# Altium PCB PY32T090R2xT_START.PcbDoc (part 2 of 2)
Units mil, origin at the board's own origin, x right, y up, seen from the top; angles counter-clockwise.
Board outline 1771.65 x 3866.06 mil, 2 copper layers (Top Layer, Bottom Layer), stack 21 mil thick; 137 components, 162 nets, 557 pads, 319 vias.
Unrouted connection lines stored in the file: 5.
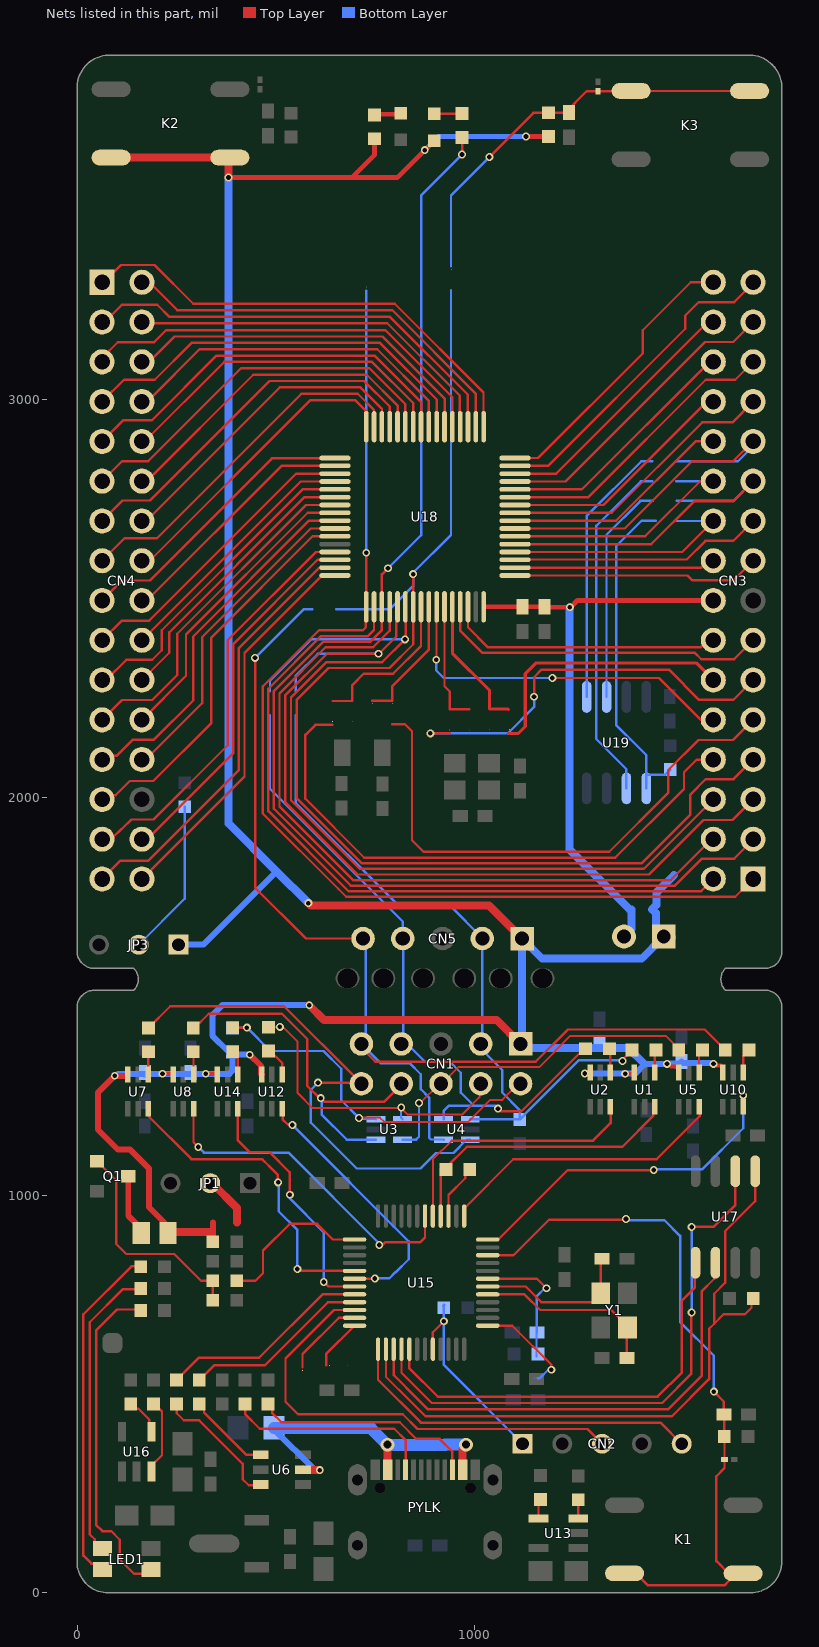
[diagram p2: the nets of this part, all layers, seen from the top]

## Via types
v1: diameter 19.68, hole 11.81, Top Layer to Bottom Layer, 161 vias
v2: diameter 19.68, hole 11.81, Top Layer to Bottom Layer, tented both sides, 146 vias
v3: diameter 35, hole 20, Top Layer to Bottom Layer, tented both sides, 8 vias
v4: diameter 30, hole 15, Top Layer to Bottom Layer, tented both sides, 2 vias
v5: diameter 40, hole 20, Top Layer to Bottom Layer, tented both sides, 2 vias

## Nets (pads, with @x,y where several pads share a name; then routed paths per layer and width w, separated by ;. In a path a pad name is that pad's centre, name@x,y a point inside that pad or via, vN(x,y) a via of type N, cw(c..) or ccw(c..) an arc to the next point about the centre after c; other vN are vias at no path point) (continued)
NetC34_2: C34.2 K3.1 K3.2 R59.2 R60.1 U21.1 | length 1037.5
  Top Layer w6: v1(1036.54,3609.79) 1147.26,3720.51 1226.51,3720.51 1281,3775 U21.1@1309.61,3775 ; U21.1@1309.96,3775.35 1385,3775.35 1385.35,3775.7 K3.1@1393,3775.7 K3.2@1691,3775.7
  Bottom Layer w6: 940,3335 940,3513.24 v1(1036.54,3609.79)
NetJP3_2: JP3.2 R50.1 | length 394.7
  Bottom Layer w6: JP3.2@155,1629.56 270.51,1745.07 R50.1@270.51,1976.45
NetLED1_2: LED1.2 R9.1 | length 846.1
  Top Layer w6: R9.1@160,710 157.67,712.33 100.33,712.33 48,660 48,171 63.8,155.2 85.86,155.2 107.53,133.53 107.53,84.16 143.82,47.87 175.08,47.87 LED1.2@186.02,58.82
NetLED1_3: LED1.3 R6.1 | length 884.3
  Top Layer w6: LED1.3@44.28,58.52 LED1.3@58.98,43.82 ; LED1.3@63.98,58.82 49.28,73.52 36.09,73.52 16,93.61 16,700.34 136.59,820.93 159.07,820.93 R6.1@160,820
NetLED1_4: LED1.4 R4.1 | length 755.1
  Top Layer w6: LED1.4@56.66,98.5 44.36,110.81 44.36,134.74 32,147.09 32,680.34 115.39,763.73 158.73,763.73 R4.1@160,765
NetLED_PA2_2: LED_PA2.2 R45.1 | length 70.4
  Top Layer w6: LED_PA2.2@898,3718 967,3718 R45.1@968,3719
NetLED_VDD*_1: LED_VDD*.1 R38.1 | length 66.4
  Top Layer w12: R38.1@748,3717 813,3717 LED_VDD*.1@814,3718
NetPYLK_A5: PYLK.A5 R1.2 | length 530.3
  Top Layer w6: R1.2@422.49,474.99 422.49,449.82 459.51,412.79 797.58,412.79 825.99,384.38 PYLK.A5@825.99,309.89
NetPYLK_B5: PYLK.B5 R3.1 | length 566
  Top Layer w6: R3.1@480,475 490.31,464.69 490.31,452.34 513.85,428.8 811.11,428.8 852.66,387.24 911.55,387.24 943.17,355.62 943.17,310.82 PYLK.B5@944.1,309.89
NetQ1_1: Q1.1 R19.1 R20.2 | length 559
  Top Layer w6: Q1.1@50,1084.8 51.97,1084.8 63.72,1073.06 63.72,1071.23 98.46,1036.49 98.46,877.34 123.86,851.94 244.45,851.94 311.61,784.78 R19.1@341.53,784.78 ; R20.2@341.52,735.88 R19.1@341.52,784.77
NetQ1_3: Q1.3 R15.1 | length 166.5
  Top Layer w6: Q1.3@125.49,1044.15 Q1.3@128.74,1047.4 ; R15.1@161.54,905 R15.1@161.54,910.91
  Top Layer w15: Q1.3@128.74,1047.4 128.74,948.28 161.54,915.49 R15.1@161.54,905
NetR2_1: R2.1 U1.4 | length 57.9
  Top Layer w6: U1.4@1452.23,1308.31 1452.23,1362.02 R2.1@1455.21,1365
NetR7_1: R7.1 U2.4 | length 57.8
  Top Layer w6: R7.1@1338.06,1365 1340.8,1362.27 U2.4@1340.8,1308.31
NetR10_1: R10.1 U5.4 | length 60.3
  Top Layer w6: U5.4@1563.66,1308.31 1563.66,1356.3 R10.1@1572.35,1365
NetR11_1: R11.1 U6.3 | length 332.9
  Top Layer w6: R11.1@250,475 250.77,474.23 250.77,451.69 268.41,434.05 306.8,434.05 416.24,324.61 416.24,285.87 431.63,270.48 459.74,270.48 U6.3@461.53,272.28
NetR12_1: R12.1 U6.1 | length 227.7
  Top Layer w6: R12.1@308.75,480 319.15,469.6 319.15,453.68 426,346.83 U6.1@471.97,346.83
NetR13_1: R13.1 U7.4 | length 59
  Top Layer w6: R13.1@173.55,1360 179.14,1354.41 U7.4@179.14,1303.31
NetR14_1: R14.1 U8.4 | length 60.8
  Top Layer w6: R14.1@280.94,1360.02 R14.1@290.82,1350.14 ; U8.4@292.86,1303.31 R14.1@292.86,1350.12
NetR18_1: R18.1 U10.4 | length 62.7
  Top Layer w6: U10.4@1675.08,1308.31 1675.08,1350.59 R18.1@1689.49,1365
NetR22_1: R22.1 U12.4 | length 75.3
  Top Layer w6: R22.1@481.63,1362.11 485.62,1362.11 515.71,1332.03 U12.4@515.71,1303.31
NetR24_2: R24.2 U13.4 | length 49.6
  Top Layer w6: U13.4@1160,187.5 1160,230 R24.2@1165,235
NetR25_2: R25.2 U13.3 | length 47.5
  Top Layer w6: U13.3@1260,187.5 R25.2@1260,235
NetR26_1: R26.1 U14.4 | length 62.8
  Top Layer w6: R26.1@391.2,1360.7 404.28,1347.62 U14.4@404.28,1303.31
NetR27_2: R27.2 U15.1 | length 256.3
  Top Layer w6: U15.1@1032.32,671.73 1094.18,671.73 1192.46,573.45 v1(1192.46,560.88)
  Bottom Layer w6: 1158.34,539.83 1163.61,539.83 1184.66,560.88 v1(1192.46,560.88)
NetR29_2: R29.2 U16.4 | length 96.1
  Top Layer w6: R29.2@135,475 147,463 154.44,463 181.5,435.94 181.5,411 U16.4@187.5,405
NetR30_2: R30.2 U16.3 | length 188.5
  Top Layer w6: U16.3@187.5,305 187.5,320 213.56,346.06 213.56,455.68 207,462.24 207,463 R30.2@195,475
NetR31_1: R31.1 U15.36 | length 129.6
  Top Layer w6: 626.21,571.75 626.21,600.26 U15.36@697.68,671.73
NetR33_1: R33.1 U15.35 | length 201.4
  Top Layer w6: 566.96,567.4 566.96,600.38 658,691.42 U15.35@697.68,691.42
NetR44_1: R44.1 R46.1 U19.1 | length 832.5
  Bottom Layer w6: U19.1@1431.15,2022.48 U19.1@1431.15,2057 ; R46.1@1455.25,2695.25 1419.25,2695.25 1355.34,2631.35 1355.34,2293.32 1355.34,2182.01 1431.15,2106.2 U19.1@1431.15,2057 ; R44.1@1491.66,2069.84 1478.82,2057 U19.1@1431.15,2057
NetR47_1: R47.1 U19.2 | length 879
  Bottom Layer w6: U19.2@1381.15,2022.48 1381.15,2070.68 1305.23,2146.59 1305.23,2308.22 1305.23,2682.23 1417.33,2794.33 1446.59,2794.33
NetR48_2: R48.2 U19.6 | length 558.8
  Bottom Layer w6: U19.6@1331.15,2252.48 1331.15,2300.47 1331.15,2660.15 1416.33,2745.33 1447,2745.33
NetR49_2: R49.2 U19.5 | length 676.7
  Bottom Layer w6: U19.5@1281.15,2252.48 1281.15,2310.25 1281.15,2707.15 1418.64,2844.64 1446.22,2844.64
OSC_32INa: R39.2 R58.2 U18.8 | length 401.7
  Top Layer w6: 642.19,2242.17 692.33,2242.17 692.33,2282.33 721,2311 795,2311 864.81,2380.81 U18.8@864.81,2478.94
OSC_32OUTa: R40.2 R61.2 U18.9 | length 325.8
  Top Layer w6: 742.01,2242.69 792.29,2242.69 792.8,2242.17 792.8,2279.8 884.49,2371.49 U18.9@884.49,2478.94
OSC_INa: R41.2 R54.2 U18.11 | length 312.6
  Top Layer w6: U18.11@923.86,2478.94 923.86,2279.14 937,2266 937,2221.03 937.26,2220.77 937.66,2221.17 985.95,2221.17
OSC_OUTa: R42.2 R56.2 U18.12 | length 343.1
  Top Layer w8: U18.12@943.55,2478.94 943.55,2362.45 1037,2269 1037,2222 1082.73,2222 1083.96,2220.77
PA0: CN3.1 R55.2 U18.1 | length 2824
  Top Layer w6: v2(727.01,2614.99) U18.1@727.01,2478.94 725.9,2477.83 725.9,2426.9 719,2420 608.21,2420 467,2278.79 467,1959.6 656.6,1770 676.6,1750 1654.82,1750 CN3.1@1699.59,1794.77
  Bottom Layer w6: v2(727.01,2614.99) 727.01,3273
PA1: CN3.2 U18.2 | length 1907.5
  Top Layer w6: U18.2@746.7,2478.94 746.7,2420.7 731.39,2405.39 613.4,2405.39 481,2272.99 481,1965.4 682.4,1764 1568.82,1764 CN3.2@1599.59,1794.77
PA2: CN3.3 R45.2 U18.3 | length 3286.8
  Top Layer w6: v2(782,2576) 766.38,2560.38 U18.3@766.38,2478.94 766.38,2420.38 737.39,2391.39 619.2,2391.39 495,2267.2 495,1971.2 688.2,1778 1503,1778 1571,1846 1652.24,1846 1699.59,1893.35 CN3.3@1699.59,1894.77 ; v1(968,3616) R45.2@968,3659
  Bottom Layer w6: v2(782,2576) 865,2659 865,3513 v1(968,3616)
PA3: CN3.4 U18.4 | length 1896.4
  Top Layer w6: U18.4@786.07,2478.94 786.07,2419.07 744.39,2377.39 625,2377.39 509,2261.4 509,1977 694,1792 1492.4,1792 1595.17,1894.77 CN3.4@1599.59,1894.77
PA4: CN3.5 R51.2 U18.5 | length 2284.6
  Top Layer w6: U18.5@805.75,2478.94 805.75,2443.91 802.98,2441.13 802.98,2439.06 802.98,2404.98 759,2361 628.4,2361 523,2255.6 523,1987.84 704.84,1806 1438,1806 1574.93,1942.93 1647.75,1942.93 CN3.5@1699.59,1994.77
  Bottom Layer w6: 550,2267 550,2306 605,2361 v2(758,2361)
PA5: CN3.6 R52.2 U18.6 | length 2301.6
  Top Layer w6: v2(824.28,2397) 767.28,2340 627.2,2340 538,2250.8 538,1992.64 710.64,1820 1424.82,1820 CN3.6@1599.59,1994.77 ; U18.6@825,2480 826.55,2478.45 v2@826.55,2398.45
  Bottom Layer w6: 485,2267 485,2294 588,2397 v2(824.28,2397)
PA6: CN3.8 R39.1 | length 1453.1
  Top Layer w6: 642.19,2182.17 599.17,2182.17 574,2157 574,1996.24 722.24,1848 1352.82,1848 1526,2021.18 1526,2063 1557.77,2094.77 CN3.8@1599.59,2094.77
PA7: CN3.9 R40.1 | length 1371.2
  Top Layer w6: 792.8,2184.13 823.97,2184.13 842,2166.1 842,1892 871,1863 1338,1863 1486,2011 1486,2068 1562,2144 1568.4,2144 1648.82,2144 CN3.9@1699.59,2194.77
PA8: CN3.10 U18.10 | length 908.5
  Top Layer w6: v2(903,2346) 903.59,2346.59 903.59,2478.35 U18.10@904.18,2478.94 ; v2(1195,2300) 1463,2300 1568.23,2194.77 CN3.10@1599.59,2194.77
  Bottom Layer w6: v2(903,2346) 903,2319 922,2300 v2(1195,2300)
PA9: CN3.11 R41.1 | length 1022.8
  Top Layer w6: v2(888.23,2160.77) 937.26,2160.77 ; v2(1149,2253) 1149,2302 1168,2321 1488,2321 1564,2245 1649.82,2245 CN3.11@1699.59,2294.77
  Bottom Layer w6: v2(888.23,2160.77) 1082.77,2160.77 1149,2227 v2(1149,2253)
PA10: CN3.12 R42.1 | length 684.9
  Top Layer w8: 1083.96,2160.77 1109.77,2160.77 1127,2178 1127,2311 1154,2338 1556.36,2338 CN3.12@1599.59,2294.77
PA11: CN3.13 U18.13 | length 845.9
  Top Layer w6: U18.13@963.23,2478.94 963.23,2419.75 962.98,2419.5 1019.48,2363 1553.19,2363 1569.13,2347.06 1651.88,2347.06 CN3.13@1699.59,2394.77
PA12: CN3.14 U18.14 | length 696.3
  Top Layer w6: U18.14@982.92,2478.94 982.92,2427.57 1033.5,2377 1567.58,2377 1585.35,2394.77 CN3.14@1599.59,2394.77
PA13: CN3.17 U18.17 | length 623.6
  Top Layer w6: U18.17@1101.02,2557.67 1534.33,2557.67 1546,2546 1650.82,2546 CN3.17@1699.59,2594.77
PA14: CN3.18 U18.18 | length 493.7
  Top Layer w6: U18.18@1113.15,2577.31 1568.83,2577.31 1586.29,2594.77 CN3.18@1599.59,2594.77
PA15: CN3.19 U18.19 | length 627
  Top Layer w6: U18.19@1113.04,2597.1 1113.77,2597.83 1532.83,2597.83 1579.77,2644.77 1649.59,2644.77 CN3.19@1699.59,2694.77
PB0: CN3.20 R46.2 U18.20 | length 611.6
  Top Layer w6: U18.20@1113.04,2616.79 1521.62,2616.79 CN3.20@1599.59,2694.77
  Bottom Layer w6: 1507,2695.26 1507.49,2694.77 CN3.20@1599.59,2694.77
PB1: CN3.21 R48.1 U18.21 | length 865.2
  Top Layer w6: U18.21@1113.04,2636.47 1443.47,2636.47 1551,2744 1648.82,2744 CN3.21@1699.59,2794.77
  Bottom Layer w6: 1507,2745.33 1650.15,2745.33 CN3.21@1699.59,2794.77
PB2: CN3.22 R47.2 U18.22 | length 676
  Top Layer w6: U18.22@1113.04,2656.16 1428.16,2656.16 1566.77,2794.77 CN3.22@1599.59,2794.77
  Bottom Layer w6: 1545.46,2794.25 1545.38,2794.33 1506.59,2794.33 1507.03,2794.77 CN3.22@1599.59,2794.77
PB3: CN3.23 R49.1 U18.23 | length 898.5
  Top Layer w6: U18.23@1113.04,2675.84 1377.05,2675.84 1545.84,2844.64 1649.46,2844.64 CN3.23@1699.59,2894.77
  Bottom Layer w6: 1506.22,2844.64 1661.64,2844.64 1699.59,2882.59 CN3.23@1699.59,2894.77
PB4: CN3.24 U18.24 | length 569.1
  Top Layer w6: U18.24@1113.04,2695.53 1355.53,2695.53 1554.77,2894.77 CN3.24@1599.59,2894.77
PB5: CN3.25 U18.25 | length 702.3
  Top Layer w6: U18.25@1113.04,2715.21 1344.21,2715.21 1571.62,2942.62 1647.44,2942.62 CN3.25@1699.59,2994.77
PB6: CN3.26 U18.26 | length 594.2
  Top Layer w6: U18.26@1113.04,2734.9 1323.9,2734.9 1583.77,2994.77 CN3.26@1599.59,2994.77
PB7: CN3.27 U18.27 | length 727.5
  Top Layer w6: U18.27@1113.04,2754.58 1285.58,2754.58 1580.77,3049.77 1654.59,3049.77 CN3.27@1699.59,3094.77
PB8: CN3.28 U18.28 | length 619.3
  Top Layer w6: U18.28@1113.04,2774.27 1269.27,2774.27 1589.77,3094.77 CN3.28@1599.59,3094.77
PB9: CN3.29 U18.29 | length 752.6
  Top Layer w6: U18.29@1113.04,2793.95 1227.95,2793.95 1578.77,3144.77 1649.59,3144.77 CN3.29@1699.59,3194.77
PB10: CN3.30 U18.30 | length 644.4
  Top Layer w6: U18.30@1113.04,2813.64 1204.64,2813.64 1585.77,3194.77 CN3.30@1599.59,3194.77
PB11: CN3.31 U18.31 | length 810.3
  Top Layer w6: U18.31@1101.02,2833.26 1184.26,2833.26 1529,3178 1529,3211 1563,3245 1652,3245 1699.59,3292.59 CN3.31@1699.59,3294.77
PB12: CN3.32 U18.32 | length 715.5
  Top Layer w6: U18.32@1101.02,2852.95 1158.95,2852.95 1422,3116 1422,3174 1542.77,3294.77 CN3.32@1599.59,3294.77
PB13: CN4.1 U18.33 | length 1195.8
  Top Layer w6: CN4.1@63.14,3294.77 67.39,3294.77 110.88,3338.26 194.84,3338.26 292.24,3240.86 798.9,3240.86 1021.74,3018.02 1021.74,2932.35 U18.33@1022.35,2931.74
PB14: CN4.2 U18.34 | length 1038.4
  Top Layer w6: CN4.2@163.04,3294.77 171.06,3286.75 190.26,3286.75 252.15,3224.86 792.27,3224.86 1001.99,3015.15 1001.99,2932.42 U18.34@1002.66,2931.74
PB15: CN4.3 U18.35 | length 1111.2
  Top Layer w6: CN4.3@63.14,3194.77 69.06,3194.77 112.72,3238.43 201.88,3238.43 232.51,3207.8 786.7,3207.8 982.63,3011.88 U18.35@982.63,2932.1
PC0: CN4.4 U18.36 | length 954.2
  Top Layer w6: CN4.4@163.04,3194.77 166.01,3191.8 780.07,3191.8 962.5,3009.38 962.5,2968.7 962.56,2968.63 962.56,2932.47 U18.36@963.23,2931.68
PC1: CN4.5 U18.37 | length 1063.2
  Top Layer w6: CN4.5@63.14,3094.77 63.14,3104.77 102.32,3143.95 193.66,3143.95 224.2,3174.5 774.75,3174.5 943.61,3005.64 U18.37@943.55,2931.68
PC2: CN4.6 U18.38 | length 922.7
  Top Layer w6: CN4.6@163.04,3094.77 181.17,3094.77 244.9,3158.5 768.12,3158.5 923.99,3002.63 U18.38@923.99,2931.82
PC3: CN4.7 U18.39 | length 1029.4
  Top Layer w6: CN4.7@63.14,2994.77 118.27,3049.9 195.47,3049.9 288.08,3142.5 761.5,3142.5 904.2,2999.8 U18.39@904.2,2931.79
PC4: CN4.8 U18.40 | length 894.9
  Top Layer w6: CN4.8@163.04,2994.77 172.35,3004.07 185.65,3004.07 308.07,3126.5 754.87,3126.5 883.82,2997.55 883.82,2968.63 883.82,2932.47 U18.40@884.55,2931.74
PC5: CN4.9 U18.41 | length 1001.7
  Top Layer w6: CN4.9@63.14,2894.77 115.85,2947.48 187.74,2947.48 350.76,3110.5 748.24,3110.5 865.08,2993.66 865.08,2931.95 U18.41@864.87,2931.74
PC6: CN4.10 U18.42 | length 870.2
  Top Layer w6: CN4.10@163.04,2894.77 166.61,2891.2 369.9,3094.5 741.6,3094.5 845.51,2990.59 845.51,2932.07 U18.42@845.18,2931.74
PC7: CN4.11 U18.43 | length 975.6
  Top Layer w6: CN4.11@63.14,2794.77 113.14,2844.77 178.64,2844.77 412.38,3078.5 734.98,3078.5 824.92,2988.55 824.92,2932.32 U18.43@825.44,2931.68 ; U18.43@824.39,2929.99 U18.43@825.82,2931.42
PC8: CN4.12 U18.44 | length 852.7
  Top Layer w6: CN4.12@173.57,2784.24 CN4.12@163.04,2794.77 164.72,2796.44 177.13,2796.44 443.2,3062.5 728.35,3062.5 805.91,2984.94 U18.44@805.91,2933
PC9: CN4.13 U18.45 | length 945.7
  Top Layer w6: CN4.13@63.14,2694.77 114.49,2746.12 183.76,2746.12 484.15,3046.5 721.72,3046.5 786.08,2982.14 U18.45@786.07,2931.68
PC10: CN4.14 U18.46 | length 809.3
  Top Layer w6: CN4.14@163.04,2694.77 173.85,2694.77 509.58,3030.5 712.27,3030.5 766.71,2976.06 U18.46@766.71,2932.01
PC11: CN4.15 U18.47 | length 916.3
  Top Layer w6: CN4.15@63.14,2594.77 119.64,2651.27 200.85,2651.27 564.08,3014.5 705.64,3014.5 746.6,2973.54 U18.47@746.6,2931.5
PC12: CN4.16 U18.48 | length 778.6
  Top Layer w6: CN4.16@163.04,2594.77 183.02,2594.77 586.75,2998.5 699.01,2998.5 727.48,2970.03 U18.48@727.48,2934.93
PC13: CN4.17 U18.49 | length 732.5
  Top Layer w6: CN4.17@63.04,2494.77 113.34,2545.07 183.07,2545.07 490,2852 596.43,2852 ; 596.43,2852.28 U18.49@626.59,2852.28 ; U18.49@627.39,2852.28 U18.49@648.34,2852.28
PC14: CN4.18 U18.50 | length 637.5
  Top Layer w6: CN4.18@163.04,2494.77 175.41,2494.77 513.97,2833.32 U18.50@660.3,2833.32
PC15: CN4.19 U18.51 | length 758.7
  Top Layer w6: CN4.19@63.14,2394.77 112.71,2444.34 181.77,2444.34 551.08,2813.65 U18.51@648.34,2813.65
PD0: CN4.20 U18.52 | length 650.6
  Top Layer w6: CN4.20@163.04,2394.77 562.27,2793.99 U18.52@648.31,2793.99
PD1: CN4.21 U18.53 | length 825
  Top Layer w6: CN4.21@63.14,2294.77 72.96,2294.77 124.14,2345.95 189.2,2345.95 212.85,2369.61 212.85,2419.8 567.21,2774.15 U18.53@660.18,2774.15
PD2: CN4.22 U18.54 | length 717.7
  Top Layer w6: CN4.22@163.14,2294.77 167.54,2299.17 231.7,2363.33 231.7,2414.6 571.68,2754.58 U18.54@660.3,2754.58
PD3: CN4.23 U18.55 | length 869.7
  Top Layer w6: CN4.23@63.14,2194.77 113.14,2244.77 189.07,2244.77 252,2307.69 252,2411.4 575.51,2734.9 U18.55@648.34,2734.9
PD4: CN4.24 U18.56 | length 773.5
  Top Layer w6: CN4.24@163.04,2194.77 273.9,2305.62 273.9,2409.14 579.97,2715.21 U18.56@660.3,2715.21
PD5: CN4.25 U18.57 | length 940
  Top Layer w6: CN4.25@63.14,2094.77 72.42,2104.05 99.28,2104.05 140.39,2145.16 193.64,2145.16 292.07,2243.59 292.07,2404.03 583.58,2695.53 U18.57@660.3,2695.53
PD6: CN4.26 U18.58 | length 835.2
  Top Layer w6: CN4.26@163.04,2094.77 172.61,2094.77 314.43,2236.59 314.43,2402.53 587.75,2675.84 U18.58@660.3,2675.84
PD7: CN4.27 U18.59 | length 996.7
  Top Layer w6: CN4.27@63.14,1994.77 73.66,2005.29 96.96,2005.29 132.69,2041.02 191.53,2041.02 337.66,2187.15 337.66,2401.49 592.33,2656.16 U18.59@660.3,2656.16
PD9: CN4.29 U18.61 | length 1050.5
  Top Layer w6: CN4.29@63.14,1894.77 68.15,1899.78 90.58,1899.78 137.14,1944.31 192.45,1944.31 379,2130.86 379,2395.19 600.6,2616.79 U18.61@660.3,2616.79
PD10: CN4.30 U18.62 | length 949
  Top Layer w6: CN4.30@163.04,1894.77 173.57,1905.29 187.19,1905.29 393,2111.1 393,2385.59 604.51,2597.1 U18.62@660.3,2597.1
PD11: CN4.31 U18.63 | length 1101
  Top Layer w6: CN4.31@63.14,1794.77 109.39,1841.02 179.44,1841.02 407,2068.58 407,2375.25 608,2576.25 659.13,2576.25 U18.63@660.3,2577.42
PD12: CN4.32 U18.64 | length 995
  Top Layer w6: CN4.32@163.04,1794.77 421,2052.72 421,2362.96 615.77,2557.73 U18.64@660.3,2557.73
PD13: CN3.7 R53.2 R60.2 U18.7 | length 3128.4
  Top Layer w6: v2(845,2561) 845.06,2560.94 845.06,2479.01 U18.7@845.12,2478.94 845.12,2384.65 785.48,2325 632,2325 552,2245 552,1998.44 716.44,1834 1419.03,1834 1542,1956.97 1542,2007.2 1580.48,2045.68 1650.5,2045.68 CN3.7@1699.59,2094.77
  Bottom Layer w6: 651,2473 787,2473 845,2531 v2(845,2561) 845,2564.36 940,2659.36 940,3275
PYLK_BOOT0: CN2.1 R28.1 U15.44 | length 514.7
  Top Layer w6: U15.44@894.53,612.68 894.53,655.07 v2(922.21,682.75)
  Bottom Layer w6: R28.1@923.26,724.4 920.49,721.63 922.21,719.9 v2(922.21,682.75) 922.21,572.79 CN2.1@1120,375
PYLK_KEY: C6.2 K1.1 K1.2 R16.1 U11.1 U15.10 | length 1795.7
  Top Layer w6: U15.10@1032.32,848.9 1097.14,848.9 1186.44,938.2 1378.2,938.2 v2(1380,940) ; K1.2@1376.55,49 1405.25,49 1435.5,18.75 1627.36,18.75 1639.02,30.41 1639.02,34.51 K1.1@1653.51,49 ; v2(1601,506) 1626,481 C6.2@1626,449 1627,448 R16.1@1627,393 1627.7,392.3 U11.1@1627.7,335 1627.7,313.7 1607.3,293.3 1607.3,80 1638.3,49 K1.1@1653.51,49 ; K1.1@1674.55,49 K1.1@1653.51,49
  Bottom Layer w6: v2(1380,940) 1383.06,936.94 1392.62,936.94 1392.69,936.88 1476.64,936.88 1516,897.52 1516,681 1601,596 v2(1601,506)
PYLK_NRST: C24.2 R36.1 U15.7 | length 341.9
  Top Layer w6: U15.7@1032.32,789.84 1156.36,789.84 v2(1180.4,765.8)
  Bottom Layer w6: R36.1@1155.12,595 1155.12,654 C24.2@1156.12,655 1156.12,746 1175.92,765.8 v2(1180.4,765.8)
PYLK_OSCIN: C19.2 U15.5 Y1.3 | length 465.6
  Top Layer w6: U15.5@1032.32,750.47 1125.05,750.47 1164.42,711.1 1343.11,711.1 1383.59,670.63 Y1.3@1383.59,666.69 1382.12,665.22 C19.2@1382.12,590
PYLK_OSCOUT: C25.2 U15.6 Y1.1 | length 399.8
  Top Layer w6: U15.6@1032.32,770.16 1127.99,770.16 1167.36,730.79 1297.03,730.79 1316.66,750.41 Y1.1@1316.66,753.31 1316.66,836.54 C25.2@1320.12,840
PYLK_SPI_CS: R35.1 U15.38 U17.1 | length 1667.6
  Top Layer w5: U15.38@776.42,612.68 776.42,543.62 837.66,482.38
  Top Layer w6: 837.66,482.38 875.95,444.09 1495.51,444.09 1588.88,537.47 1588.88,663.88 1601.77,676.77 ; R35.1@1700,740 1695.62,735.62 1695.62,716.69 1679.36,700.42 1625.42,700.42 1601.77,676.77 ; U17.1@1705,1060 1705,985 1629.69,909.69 1629.69,780.01 1601.77,752.09 1601.77,676.77
PYLK_SPI_MISO: U15.40 U17.2 | length 1437.2
  Top Layer w6: U15.40@815.79,612.68 815.79,553.3 891.8,477.3 1471,477.3 1543.9,550.2 1543.9,703.9 v2(1545,705) ; v2(1545,920) 1600,920 1655,975 U17.2@1655,1060
  Bottom Layer w6: v2(1545,705) v2(1545,920)
PYLK_SPI_MOSI: U15.41 U17.5 | length 1077.9
  Top Layer w6: U15.41@835.47,612.68 835.47,564.49 906.66,493.3 1459.42,493.3 1520.53,554.41 1520.53,735.09 1553.13,767.69 1553.13,828.13 U17.5@1555,830
PYLK_SPI_SCK: U15.39 U17.6 | length 1208.9
  Top Layer w6: U15.39@796.1,612.68 796.1,547.36 856.32,487.14 882.17,461.3 1486.07,461.3 1570.21,545.44 1570.21,758.06 1601.94,789.79 1601.94,826.94 U17.6@1605,830
SWD_SCK: CN2.5 U15.37 | length 906.8
  Top Layer w6: U15.37@756.73,612.68 756.73,535.75 864.48,428 1467,428 CN2.5@1520,375
SWD_SDA: CN2.3 U15.34 | length 1172.2
  Top Layer w6: U15.34@697.68,711.1 646.11,711.1 524.05,589.04 524.05,480.71 555.57,449.2 818.75,449.2 855.95,412 1283,412 CN2.3@1320,375
T_RESET: CN1.9 CN5.5 R18.2 R53.1 U4.4 | length 2728.9
  Top Layer w6: v2(447.56,2350.56) 447.56,1772.77 575.33,1645 CN5.5@718.94,1645 ; CN1.9@722.78,1362.78 750.2,1335.36 1152.91,1335.36 1233.99,1416.44 1578.06,1416.44 R18.2@1629.49,1365
  Bottom Layer w6: v2(447.56,2350.56) 569.51,2472.51 590.51,2472.51 591,2473 ; CN5.5@718.94,1645 726,1637.94 726,1391 CN1.9@715,1380 763.22,1331.78 836.02,1331.78 864.1,1303.69 864.1,1266.42 885.15,1245.37 885.15,1144.31 889.61,1139.85 921.09,1139.85 U4.4@921.54,1139.41
T_RESETa: U10.3 U15.12 | length 870.1
  Top Layer w6: U15.12@1032.32,888.27 1058.79,888.27 1233.47,1062.96 1321.53,1062.96 v2(1449.91,1062.96) ; v2(1674.82,1250.7) 1675.08,1250.44 U10.3@1675.08,1221.69
  Bottom Layer w6: v2(1449.91,1062.96) 1451.65,1064.7 1571.4,1064.7 1674.82,1168.11 v2(1674.82,1250.7)
T_RTCK_DTRa: U5.3 U15.13 | length 731.2
  Top Layer w6: U15.13@973.27,947.32 973.27,966.57 1096.7,1090 1456.99,1090 1565.18,1198.19 1565.18,1220.16 U5.3@1563.66,1221.69
T_RTCK_VCP_DTR: CN1.6 R10.2 U3.5 | length 868.3
  Top Layer w5: v2(859.81,1231.67) 863.24,1231.67 911.57,1280 CN1.6@915,1280 916.63,1280 958.49,1321.86 1161.73,1321.86 1240.3,1400.44 1479.98,1400.44 1500.35,1380.07 1500.35,1377 R10.2@1512.35,1365
  Bottom Layer w6: U3.5@818.46,1139.41 852.51,1139.41 859.81,1146.71 v2(859.81,1231.67)
T_TCK_SWCLK: CN1.7 CN5.4 R7.2 R52.1 U4.5 | length 1695.8
  Top Layer w6: CN1.7@820,1390 CN1.7@821.35,1391.35 ; CN5.4@820,1645 CN5.4@821.35,1643.65 ; v2(1058.5,1217.32) 1065.14,1210.69 1116.96,1210.69 1271.28,1365 R7.2@1278.06,1365
  Bottom Layer w6: 485,2207 485,2021.65 818.94,1687.71 CN5.4@818.94,1645 820,1643.94 820,1385 CN1.7@815,1380 ; CN1.7@822.5,1387.5 875.47,1334.53 937.65,1334.53 964.6,1307.57 964.6,1257.54 997.14,1225 ; U4.5@921.54,1190.59 921.54,1211.54 935,1225 997.14,1225 ; v2(1058.5,1217.32) 1050.82,1225 997.14,1225
T_TCK_SWCLKa: U2.3 U15.17 | length 668.1
  Top Layer w5: U15.17@894.53,947.32 894.53,1089.76 941.77,1137
  Top Layer w6: 941.77,1137 1047.62,1137 1297.43,1137 1341.41,1180.98 1341.41,1221.08 U2.3@1340.8,1221.69
T_TDI_VCP_TX: CN1.4 R22.2 U3.4 | length 783.1
  Top Layer w5: R22.2@481.63,1422.11 517.9,1422.11 554.54,1385.48 554.54,1256.62 592.29,1218.86 v2@815,1218.86 ; R22.2@481.63,1425.11 R22.2@483.13,1423.61 ; v2@815.02,1218.86 831.78,1202.11 967.76,1202.11 1011.56,1245.9 1011.56,1276.56 CN1.4@1015,1280
  Bottom Layer w5: v2@815.06,1219.94 815.06,1194 U3.4@818.46,1190.59
  other v1: 509.96,1422.98
  other v2: 815,1220
T_TDI_VCP_TXa: U12.3 U15.30 | length 672.4
  Top Layer w6: U12.3@515.71,1216.69 516.93,1215.47 516.93,1190.37 529.24,1178.06 539.56,1178.06 v2(541.31,1176.31) ; U15.30@697.68,789.84 748.02,789.84 v2(748.76,790.58)
  Bottom Layer w6: v2(541.31,1176.31) 834.09,883.53 834.09,838.92 801.56,806.38 800.71,806.38 784.91,790.58 v2(748.76,790.58)
T_TDO_SWO: CN1.10 R13.2 U4.3 | length 1333.3
  Top Layer w6: R13.2@179.66,1420.08 234.47,1474.9 520.1,1474.9 CN1.10@708.51,1286.49 ; v2(605.87,1282.75) 606.54,1282.08 704.1,1282.08 CN1.10@708.51,1286.49 ; CN1.10@715,1280 CN1.10@708.51,1286.49
  Bottom Layer w6: v2(605.87,1282.75) 587.83,1264.72 587.83,1182.08 703.06,1066.86 863.29,1066.86 902.42,1105.99 946.45,1105.99 979.88,1139.41 U4.3@988.46,1139.41 U4.3@986.15,1137.1
T_TDO_SWOa: U7.3 U15.29 | length 807.7
  Top Layer w6: U7.3@179.14,1216.69 179.14,1198.86 287.46,1090.54 465.08,1090.54 471.63,1084 472.01,1084 489,1067.01 489,1066.63 504.93,1050.7 504.93,1032.69 v2(505.62,1032) ; v2(553.88,814.33) 558.68,809.53 641.55,809.53 U15.29@697.68,809.53
  Bottom Layer w6: v2(505.62,1032) 506.95,1030.68 506.95,958.93 553.88,912 v2(553.88,814.33)
T_TMS_SWDIO: CN1.3 CN5.2 R2.2 R5.2 R51.1 U4.1 | length 1809.1
  Top Layer w6: CN5.2@1013.3,1651.7 1020,1645 CN5.2@1019.37,1644.37 ; CN1.3@1019.37,1366.19 CN1.3@1025.56,1360 ; v2@1371.62,1335.17 1371.62,1340.47 1383.21,1352.06 1383.21,1353 R2.2@1395.21,1365
  Bottom Layer w6: 550,2207 550,1986.24 807.24,1729 936,1729 CN5.2@1019.47,1645.53 ; U4.1@988.77,1190.29 R5.2@1112.71,1190.29 ; CN1.3@1015,1380 1019,1384 1019,1644.94 CN5.2@1018.94,1645 ; CN1.3@1023.59,1359.7 1068.86,1314.42 1068.86,1257.89 1112.71,1214.04 R5.2@1112.71,1190.29 ; R5.2@1113,1190 R5.2@1112.71,1190.29 ; v2(1371.43,1337.07) 1369.25,1339.25 1261.67,1339.25 1126,1203.58 1126,1203 1113.29,1190.29 R5.2@1112.71,1190.29
T_TMS_SWDIOa: R32.1 U1.3 U15.16 | length 723.8
  Top Layer w6: U15.16@914.21,947.32 R32.1@914.21,1067.37 ; R32.1@927.46,1064.37 927.46,1068.99 980.12,1121.65 1036.7,1121.65 1371.22,1121.65 1448.34,1198.77 1448.34,1217.8 U1.3@1452.23,1221.69
T_TMS_SWDIOa_OUT: R32.2 U15.15 | length 143.2
  Top Layer w6: U15.15@933.9,947.32 933.9,1000.64 975.82,1042.56 R32.2@975.82,1073.16
T_TRST_RTSa: U8.3 U15.18 | length 840.3
  Top Layer w6: U8.3@292.86,1216.69 292.86,1132.86 v2(304.82,1120.9) ; v2(759.92,874.35) 763.83,870.44 774.54,881.16 862.39,881.16 874.84,893.6 U15.18@874.84,947.32
  Bottom Layer w6: v2(304.82,1120.9) 318.81,1106.91 531.65,1106.91 759.92,878.64 v2(759.92,874.35)
T_TRST_VCP_RTS: CN1.8 R14.2 U3.1 | length 935
  Top Layer w6: R14.2@292.3,1420.1 295.54,1420.1 331.24,1455.8 515.25,1455.8 578.58,1392.47 578.58,1274.56 609.4,1243.73 v2(612.86,1243.73) 621.6,1235 772.67,1235 820,1282.33 CN1.8@820,1290
  Bottom Layer w6: v2(612.86,1243.73) 615,1241.6 615,1202.6 678.19,1139.41 U3.1@751.54,1139.41
T_VCP_RX: CN1.2 R23.1 R26.2 U3.3 | length 1000.9
  Top Layer w5: v2(708.97,1193.74) 710.23,1195 761.42,1195 772.45,1183.97 983.91,1183.97 1039.3,1239.36 1069.36,1239.36 CN1.2@1120,1290
  Top Layer w6: R26.2@391.2,1420.7 426.7,1420.7 v1(427,1421) ; R26.2@391.2,1431.85 R26.2@391.32,1431.97
  Bottom Layer w6: R23.1@391,1420 392,1421 v1(427,1421) 485.72,1362.28 619.26,1362.28 664.05,1317.5 664.05,1238.66 v2(708.97,1193.74) 708.23,1193 708.23,1191.77 750.36,1191.77 U3.3@751.54,1190.59
T_VCP_RXa: U14.3 U15.31 | length 636
  Top Layer w6: U14.3@404.28,1216.69 404.28,1137.29 433.27,1108.3 483.54,1108.3 534.4,1057.43 534.4,1001.38 v2(535,1000.78) ; v2(620.4,781.75) 631.99,770.16 U15.31@697.68,770.16
  Bottom Layer w6: v2(535,1000.78) 535,991.42 620.4,906.02 v2(620.4,781.75)
TVDD: C12.2 C13.2 C14.2 C15.2 CN1.1 CN5.1 JP2.1 JP3.1 K2.1 K2.2 LED_PA2.1 R15.2 R17.2 R23.2 R34.2 R37.1 R38.2 R43.1 R59.1 U1.6 U2.6 U5.6 U7.6 U8.6 U10.6 U12.6 U14.6 | length 7982
  Top Layer w6: U8.6@241.67,1303.31 U8.6@244.56,1306.2 ; U14.6@353.1,1303.31 U14.6@355.99,1306.2
  Top Layer w10: v2(215,1305) 239.98,1305 U8.6@241.67,1303.31 ; v1@325,1305 351.41,1305 U14.6@353.1,1303.31 ; v2(1276.57,1305.72) 1279.15,1308.31 U2.6@1289.62,1308.31 ; v1(1377.88,1305.09) 1399.07,1305.09 1399.16,1305 1401.05,1306.89 U1.6@1401.05,1308.31 ; v2(1483,1330) 1485.62,1330 1492.63,1322.99 1510.58,1322.99 1512.47,1321.1 U5.6@1512.47,1308.31 ; v2@1608.68,1326.1 1618.91,1326.1 1623.9,1321.1 U10.6@1623.9,1308.31
  Top Layer w12: v2(381,3558) 691,3558 ; R38.2@748,3657 748,3615 691,3558 ; LED_PA2.1@898,3651 805,3558 691,3558 ; v2(1128.79,3661) R59.1@1185,3661
  Top Layer w15: v2(95,1300) 52.5,1257.5 52.5,1164.78 103.07,1114.2 133.42,1114.2 180.53,1067.09 180.53,969.95 220.52,929.96 220.52,912.95 R15.2@228.46,905 R15.2@230.24,906.78 ; v2@95.63,1299.37 U7.6@127.35,1299.37 ; 338.07,906.78 342.08,902.77 ; R17.2@342.08,874.02 342.08,902.77 ; 342.08,931.52 342.08,902.77 ; v1(434.28,1353.05) 462.84,1324.49 462.84,1305 U12.6@464.53,1303.31
  Top Layer w20: K2.2@83,3609 381,3609 v2(381,3558) ; R15.2@230.24,906.78 338.07,906.78 ; v1(581.61,1733.99) 587.6,1728 1035.94,1728 CN5.1@1118.94,1645 ; v1(583.63,1477.38) 620.91,1440.1 1054.9,1440.1 CN1.1@1115,1380
  Bottom Layer w12: v2(874,3627) 908,3661 v2(1128.79,3661)
  Bottom Layer w15: v2(95,1300) 98.79,1300 103.67,1304.88 C15.2@168.87,1304.88 ; C15.2@170,1303.74 C15.2@168.87,1304.88 ; v2@214.88,1304.88 C15.2@168.87,1304.88 ; v2(215,1305) v1(323.77,1305) 383,1305 391,1313 R23.2@391,1360 380.76,1360 340,1400.76 340,1452 365.38,1477.38 v1(583.63,1477.38) ; JP3.1@255,1629.56 317.56,1629.56 501.8,1813.8 ; R23.2@391,1353.05 v1(434.28,1353.05) ; v2(1276.57,1305.72) 1377.25,1305.72 v1@1377.25,1303.25 ; v1@1377.65,1305.09 v1(1377.88,1305.09) 1378.15,1305.36 1403.36,1305.36 1428,1330 v2(1483,1330) 1483.9,1330.9 1514.7,1330.9 C12.2@1519.4,1335.6 ; JP2.1@1475,1647.02 JP2.1@1498.85,1647.02 ; C12.2@1519.4,1331.92 1598.08,1331.92 v2(1600,1330)
  Bottom Layer w20: v2(381,3558) 381,1934.6 501.8,1813.8 v1(581.61,1733.99) ; CN1.1@1118.94,1383.94 CN5.1@1118.94,1645 1169.5,1594.44 1419.44,1594.44 JP2.1@1472.02,1647.02 ; CN1.1@1122.04,1388.26 1143.46,1370 1313.8,1370 1386,1370 1426,1330 ; JP2.1@1475,1650 1455,1670 1455,1708.86 R37.1@1445.5,1718.35 1457,1729.85 1457,1760.39 1501.1,1804.5
TVDD*: JP1.2 R34.1 | length 129
  Top Layer w20: JP1.2@335,1030 339.73,1030 402.08,967.65 402.08,931.52
TVDD_DISCHARGE_EN: R19.2 U15.25 | length 404.9
  Top Layer w6: R19.2@401.53,784.78 448.51,784.78 467.48,803.75 467.48,860.55 534.58,927.66 603.61,927.66 643,888.27 U15.25@697.68,888.27
USB_DM: R11.2 U15.32 | length 536.9
  Top Layer w6: R11.2@250,535 306.4,591.4 458.28,591.4 617.36,750.47 U15.32@697.68,750.47
USB_DP: R12.2 U15.33 | length 471.3
  Top Layer w6: R12.2@307.5,535 344.45,571.95 471.73,571.95 630.56,730.79 U15.33@697.68,730.79
VBUS_PYLK: F1.1 PYLK.A4 PYLK.A9 PYLK.B4 PYLK.B9 U6.5 | length 804.3
  Top Layer w10: PYLK.A4@774.81,309.89 PYLK.B9@786.62,309.89 ; PYLK.B4@963.78,309.88 PYLK.A9@975.6,309.88
  Top Layer w20: U6.5@568.15,310 568.98,309.17 609.58,309.17 v2(610.2,308.55) ; PYLK.B9@781.05,327.56 v3@781.05,371.45 ; PYLK.B4@969.21,328.38 v3@969.21,362.19
  Bottom Layer w15: F1.1@494.98,415 494.98,414 494.98,411.75 597.28,309.45 609.31,309.45 v2(610.2,308.55)
  Bottom Layer w20: v3@977.13,372.01 v3(977.62,372.5)
  Bottom Layer w30: F1.1@494.98,414 738.5,414 v3(780,372.5) ; v3@780.49,372.01 925.68,372.01 ; 925.68,373.41 v3@976.72,373.41
VDD: C27.2 C28.2 CN3.16 JP2.2 R37.2 U18.16 | length 1484.3
  Top Layer w6: U18.16@1022.35,2481.63 U18.16@1024.98,2479 ; CN3.16@1585.79,2494.77 CN3.16@1599.59,2494.77
  Top Layer w12: U18.16@1024.98,2479 C27.2@1120,2479 1169,2479 1170,2478 1241.08,2478 1257.85,2494.77 CN3.16@1585.79,2494.77
  Bottom Layer w20: v2(1239,2478) 1238,2477 1238,1869.12 1388.77,1718.35 ; JP2.2@1375,1650 1393.75,1668.75 1393.75,1718.35
pads on no net: PYLK. PYLK.A8 PYLK.B8 U15.42 U15.45

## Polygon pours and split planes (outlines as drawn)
GND on Top Layer "NONET_L-01_P-001" (solid, remove dead copper, pour order 4): 5,3865 1770,3865 1770,0 -3.49,0
GND on Bottom Layer "NONET_L-01_P-001" (solid, remove dead copper, pour order 3): 5,3865 1770,3865 1770,0 -3.49,0

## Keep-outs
Keep-Out Layer:
  lines w6: 0,78.74 0,1470 ; 0,1615 0,3779.53 ; 42.5,1515 142.5,1515 ; 42.5,1570 142.5,1570 ; 78.74,0 1692.91,0 ; 78.74,3866.06 1692.91,3866.06 ; 215,1515 565,1515 585,1515 ; 215,1570 565,1570 585,1570 ; 1260,1515 1280,1515 1560,1515 ; 1260,1570 1280,1570 1560,1570 ; 1630,1515 1730,1515 ; 1630,1570 1730,1570 ; 1771.65,78.74 1771.65,1473.35 ; 1771.65,1611.65 1771.65,3779.53
  lines w8: 0,78.74 ccw(c78.74,78.74) 78.74,0 ; 0,1470 cw(c43.75,1471.25) 42.5,1515 ; 0,1615 ccw(c43.75,1613.75) 42.5,1570 ; 0,3779.53 cw(c82.64,3783.43) 78.74,3866.06 ; 142.5,1515 ccw(c115,1542.5) 142.5,1570 ; 215,1515 cw(c242.5,1542.5) 215,1570 ; 585,1515 ccw(c557.5,1542.5) 585,1570 ; 1260,1515 cw(c1287.5,1542.5) 1260,1570 ; 1560,1515 ccw(c1532.5,1542.5) 1560,1570 ; 1630,1515 cw(c1657.5,1542.5) 1630,1570 ; 1692.91,0 ccw(c1692.91,78.74) 1771.65,78.74 ; 1692.91,3866.06 cw(c1689.02,3783.43) 1771.65,3779.53 ; 1730,1515 cw(c1730,1473.35) 1771.65,1473.35 ; 1730,1570 ccw(c1730,1611.65) 1771.65,1611.65

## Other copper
Top Layer:
  pour cut-out: 1655,1370 1665,1370 1665,1360 1655,1360
  pour cut-out: 275,490 285,490 285,480 275,480
  pour cut-out: 275,525 285,525 285,515 275,515
  pour cut-out: 330,525 335.5,525 335.5,503 330,503
  pour cut-out: 330,490 340,490 340,480 330,480
  region net 5V_USB_CHGR: 385,235 395,245 420,245 465,200 510,200 530,180 660,180 660,120 515,120 515,140 490,165 435,165 400,200 385,215
  region net 3V3_PYLK: 240,315 290,315 310,295 355,295 360,290 360,250 345,235 345,165 362.5,147.5 355,140 293.39,140 293.39,153.49 305,165.1 305,230 280,255 240,255
  region net 3V3_PYLK: 1095,155 1105,165 1125,165 1135,155 1135,130 1140,125 1185,125 1190,120 1190,105 1185,100 1130,100 1095,135
  region net 3V3_USB_PYLK: 1227.5,120 1300,120 1315,135 1335,135 1345,125 1345,105 1330,90 1315,90 1290,65 1290,25 1225,25 1225,118.33
  pour cut-out: 390,495 400,495 400,485 390,485
  pour cut-out: 445,495 455,495 455,485 445,485
  pour cut-out: 1627.43,1037 1637.43,1037 1637.43,1027 1627.43,1027
  pour cut-out: 1675,1075 1685,1075 1685,1065 1675,1065

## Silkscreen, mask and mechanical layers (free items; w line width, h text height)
Top Overlay:
  drawing of 1057 lines, arcs and shapes, not listed
  text "USER_PA0" at 75,3485.66 h60
  text "NRST" at 1465,3475.64 h60
  text "PB13" at 225,3286.53 h50
  text "PB12" at 1295,3286.1 h50
  text "PB14" at 355,3285.46 h50
  text "PB11" at 1430,3285 h50
  text "PB15" at 225,3186.34 h50
  text "PC0" at 355,3185.24 h50
  text "PB10" at 1295,3185.4 h50
  text "PB9" at 1430,3184.78 h50
  text "PY32T090-START V2.0" at 645,3104.17 h65
  text "PC1" at 225,3084.61 h50
  text "PB8" at 1295,3085.26 h50
  text "PB7" at 1430,3084.57 h50
  text "PC2" at 355,3084.01 h50
  text "2025-06" at 824.95,3019.47 h65
  text "PB6" at 1295,2984.05 h50
  text "PC3" at 225,2983.41 h50
  text "PC4" at 355,2982.78 h50
  text "PB5" at 1430,2983.35 h50
  text "PB3" at 1430,2883.78 h50
  text "PC5" at 225,2882.68 h50
  text "PC6" at 355,2882.02 h50
  text "PB4" at 1295,2882.38 h50
  text "PC7" at 225,2781.95 h50
  text "PC8" at 355,2782.33 h50
  text "PB2" at 1295,2781.7 h50
  text "PB1" at 1430,2782.07 h50
  text "PB0" at 1295,2682.74 h50
  text "PC9" at 225,2682.29 h50
  text "PA15" at 1430,2681.96 h50
  text "PC10" at 355,2681.03 h50
  text "PA14" at 1295,2582.17 h50
  text "PC11" at 225,2581.02 h50
  text "PC12" at 355,2581.45 h50
  text "PA13" at 1430,2581.21 h50
  text "VDD" at 1295,2482.04 h50
  text "GND" at 1430,2481.53 h50
  text "PC13" at 225,2481.36 h50
  text "PC14" at 355,2480.15 h50
  text "PA12" at 1295,2380.83 h50
  text "PA11" at 1430,2380.89 h50
  text "PC15" at 225,2379.63 h50
  text "PD0" at 355,2378.93 h50
  text "PA10" at 1295,2280.22 h50
  text "PA9" at 1435,2279.68 h50
  text "PD2" at 355,2278.7 h50
  text "PD1" at 225,2277.9 h50
  text "PD4" at 355,2178.58 h50
  text "PA8" at 1295,2179.09 h50
  text "PD3" at 225,2177.71 h50
  text "PA7" at 1430,2177.93 h50
  text "PD13" at 1430,2078.78 h50
  text "PD6" at 355,2077.82 h50
  text "PA6" at 1295,2077.95 h50
  text "PD5" at 225,2077.09 h50
  text "PA5" at 1295,1978.35 h50
  text "PD7" at 225,1977 h50
  text "PD8" at 355,1977.06 h50
  text "PA4" at 1430,1976.96 h50
  text "PA3" at 1295,1876.67 h50
  text "PD9" at 225,1876.27 h50
  text "PD10" at 355,1876.3 h50
  text "PA2" at 1430,1875.75 h50
  text "PA0" at 1430,1776 h50
  text "PD11" at 225,1775 h50
  text "PD12" at 355,1775 h50
  text "PA1" at 1295,1775 h50
  text "VDD*" at 1100,1710.51 h45
  text "NRST" at 630,1710.48 h45
  text "SWC" at 760,1710.48 h45
  text "GND" at 870,1710.48 h45
  text "SWD" at 985,1710.48 h45
  text "VDD" at 1326.2,1699.99 h45
  text "VDD*" at 1436.9,1699.99 h45
  text "VDD" at 250,1686 h45
  text "GND" at 5,1685.48 h45
  text "BOOT0" at 105,1685.48 h45
  text "BOOT_SEL" at 315,1632.99 h45
  text "IDD" at 1527.1,1632.2 h50
  text "NRST" at 670,1445.43 h40
  text "SWC" at 790,1445.43 h40
  text "GND" at 896.86,1445.43 h40
  text "SWD" at 996.31,1445.43 h40
  text "VDD*" at 1090,1445.46 h40
  text "DTR" at 896.86,1175.88 h40
  text "TX" at 996.31,1175.88 h40
  text "RX" at 1090,1175.88 h40
  text "SWO" at 670,1175.43 h40
  text "RTS" at 790,1175.43 h40
  text "VDD_SEL" at 513,1079.99 h45
  text "5V" at 190,1075.64 h60
  text "3V3" at 410,1075.64 h60
  text "VDD*" at 265,1075 h60
  text "DIO" at 1282,425.54 h50
  text "GND" at 1374,425.54 h50
  text "CLK" at 1481,425.54 h50
  text "VDD" at 1170,425 h50
  text "BT0" at 1078,423.54 h50
  text "PY-LINK V2.0" at 691,397.47 h65
Bottom Overlay:
Mechanical 1:
  lines w6: 215,1515 565,1515 585,1515 ; 215,1570 565,1570 585,1570 ; 1260,1515 1280,1515 1560,1515 ; 1260,1570 1280,1570 1560,1570
  lines w8: 215,1515 cw(c242.5,1542.5) 215,1570 ; 585,1515 ccw(c557.5,1542.5) 585,1570 ; 1260,1515 cw(c1287.5,1542.5) 1260,1570 ; 1560,1515 ccw(c1532.5,1542.5) 1560,1570

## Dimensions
42.5,1570 to 78.74,3866.06 on Mechanical 1
1771.65,78.74 to 1835,3865 on Mechanical 1
78.74,0 to -5,1505 on Mechanical 1
0,0 to 1770,-60 on Mechanical 1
